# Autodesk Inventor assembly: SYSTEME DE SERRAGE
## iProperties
Shininess: 41.0
Angle Display Precision: 2
Document Length Units: 11269
Document Angle Units: 11279
Document Time Units: 11290
Document Mass Units: 11283
Document Length Units Precision: 3
Document Angle Units Precision: 2
Part Number: SYSTEME DE SERRAGE
Document SubType Name: Assembly
Density: 0.0
Volumn: 0.0
Area: 0.0
PropertySet Name: Model Information
Control State: 0
Master: False
Checked Out: False
